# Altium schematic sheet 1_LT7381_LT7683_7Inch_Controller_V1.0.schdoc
size 431 x 309 mm; Symbol: Sheet-Symbol_A3; Device: Sheet-Symbol_A3; @Page Name: LT7381/LT7683_7Inch_Controller_V1.0; @Create Date: 2022-11-14; @Page Count: 1; @Page No: 1; @Project Name: LT7381(LT7683)_7Inch_Controller; @Schematic Name: LT7381/LT7683_7Inch_Controller_V1.0; @Update Date: 2023-04-10; Company: LEVETOP; Page Size: A3; Version: V1.0
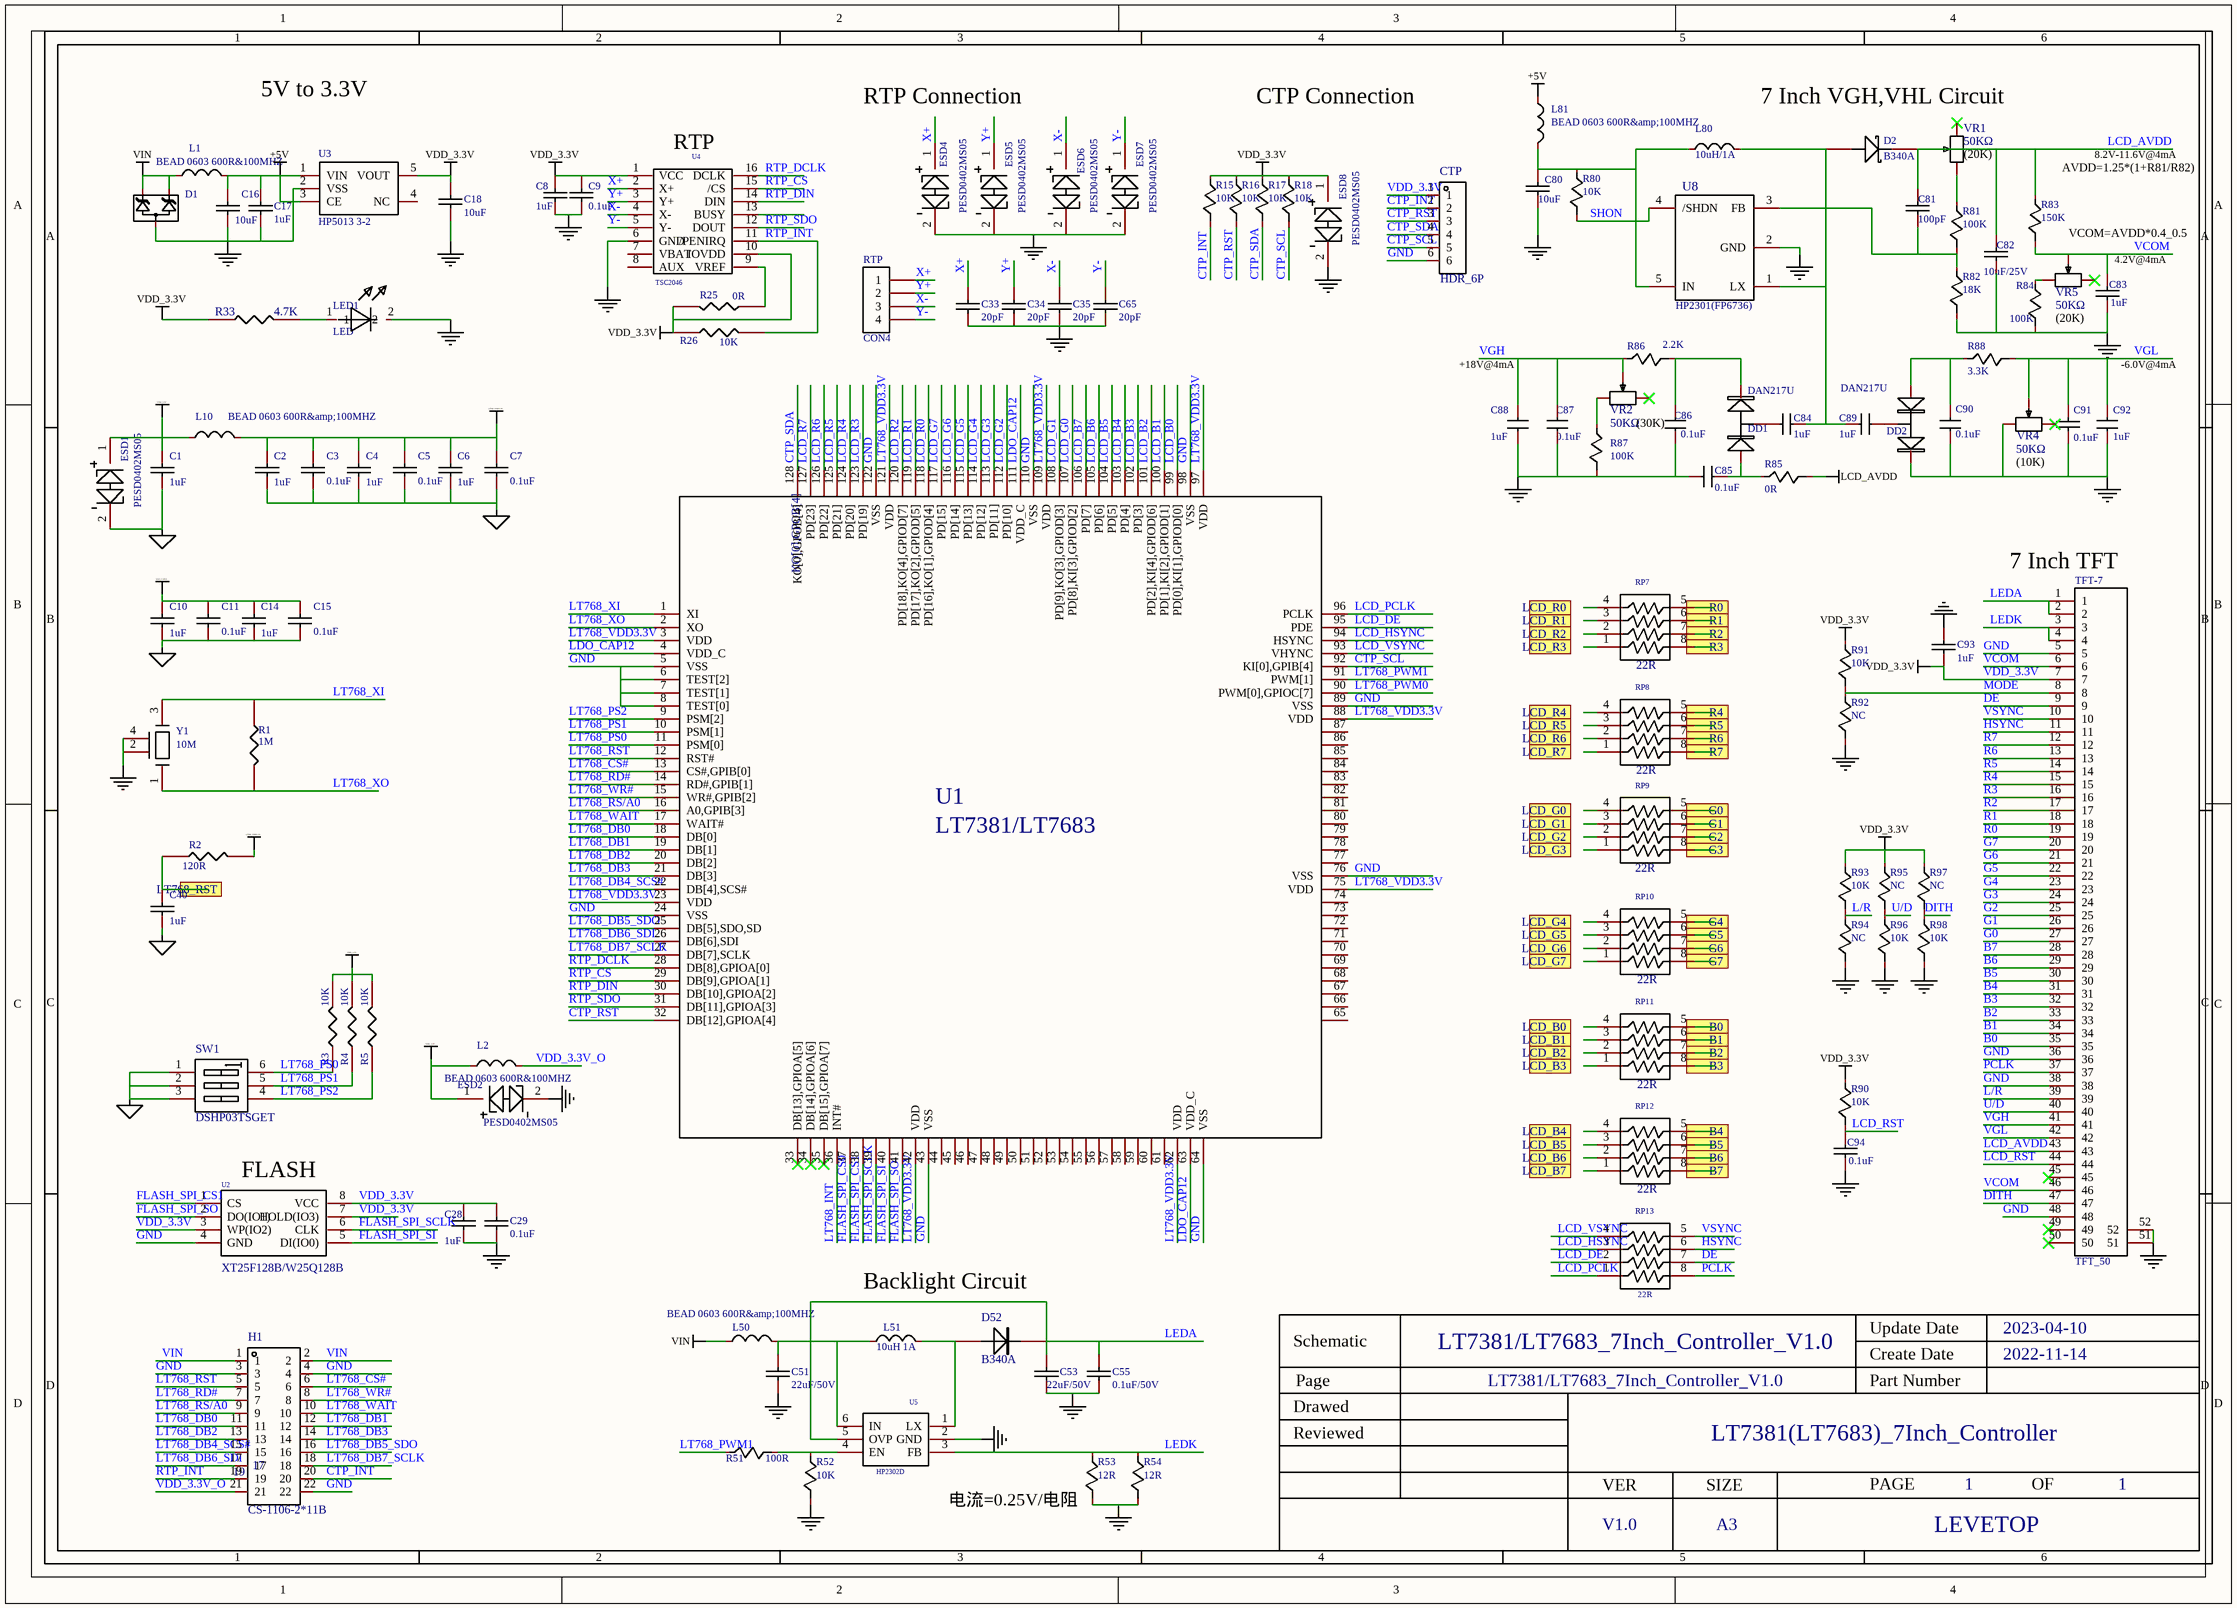
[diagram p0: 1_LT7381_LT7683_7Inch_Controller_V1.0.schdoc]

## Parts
C1  1uF  [C0603]
C2  1uF  [C0603]
C3  0.1uF  [C0603]
C4  1uF  [C0603]
C5  0.1uF  [C0603]
C6  1uF  [C0603]
C7  0.1uF  [C0603]
C8  1uF  [C0603]
C9  0.1uF  [C0603]
C10  1uF  [C0603]
C11  0.1uF  [C0603]
C14  1uF  [C0603]
C15  0.1uF  [C0603]
C16  10uF  [C0805]
C17  1uF  [C0603]
C18  10uF  [C0805]
C28  1uF  [C0603]
C29  0.1uF  [C0603]
C33  20pF  [C0603]
C34  20pF  [C0603]
C35  20pF  [C0603]
C40  1uF  [C0603]
C51  22uF/50V  [C0805_1]
C53  22uF/50V  [C0805_1]
C55  0.1uF/50V  [C0603]
C65  20pF  [C0603]
C80  10uF  [C0603]
C81  100pF  [C0603]
C82  10uF/25V  [C0603]
C83  1uF  [C0603]
C84  1uF  [C0603]
C85  0.1uF  [C0603]
C86  0.1uF  [C0603]
C87  0.1uF  [C0603]
C88  1uF  [C0603]
C89  1uF  [C0603]
C90  0.1uF  [C0603]
C91  0.1uF  [C0603]
C92  1uF  [C0603]
C93  1uF  [C0603]
C94  0.1uF  [C0603]
CTP  HDR_6P  [SIP-6P]
D1  MMBZ5V6A  [SOT-23]  (value not drawn)
D2  B340A  [DO-214]
D52  B340A  [DO-214]
DD1  DAN217U  [SOT23]
DD2  DAN217U  [SOT23]
ESD1  PESD0402MS05  [ESD0402]
ESD2  PESD0402MS05  [ESD0402]
ESD4  PESD0402MS05  [ESD0402]
ESD5  PESD0402MS05  [ESD0402]
ESD6  PESD0402MS05  [ESD0402]
ESD7  PESD0402MS05  [ESD0402]
ESD8  PESD0402MS05  [ESD0402]
H1  NUMBER: 19  NAME: 17  [HDR-TH_22P-P2.54-V-M-R2-C11-S2.54]  (hidden comment: CS-1106-2*11B)
L1  BEAD 0603 600R&100MHZ  [L0603]
L2  BEAD 0603 600R&100MHZ  [L0603]
L10  BEAD 0603 600R&amp;100MHZ  [L0603]
L50  BEAD 0603 600R&amp;100MHZ  [L0603]
L51  10uH 1A  [IND8A]
L80  10uH/1A  [IND8A]
L81  BEAD 0603 600R&amp;100MHZ  [L0603]
LED1  LED  [0603LED]
R1  1M  [R0603]
R2  120R  [R0603]
R3  10K  [R0603]
R4  10K  [R0603]
R5  10K  [R0603]
R15  10K  [R0603]
R16  10K  [R0603]
R17  10K  [R0603]
R18  10K  [R0603]
R25  0R  [R0603]
R26  10K  [R0603]
R33  4.7K  [R0603]
R51  100R  [R0603]
R52  10K  [R0603]
R53  12R  [R0603]
R54  12R  [R0603]
R80  10K  [R0603]
R81  100K  [R0603]
R82  18K  [R0603]
R83  150K  [R0603]
R84  100K  [R0603]
R85  0R  [R0603]
R86  2.2K  [R0603]
R87  100K  [R0603]
R88  3.3K  [R0603]
R90  10K  [R0603]
R91  10K  [R0603]
R92  NC  [R0603]
R93  10K  [R0603]
R94  NC  [R0603]
R95  NC  [R0603]
R96  10K  [R0603]
R97  NC  [R0603]
R98  10K  [R0603]
RP7  22R  [8R4R]
RP8  22R  [8R4R]
RP9  22R  [8R4R]
RP10  22R  [8R4R]
RP11  22R  [8R4R]
RP12  22R  [8R4R]
RP13  22R  [8R4R]
RTP  CON4  [SIP-4P]
SW1  DSHP03TSGET  [SW-SMD_6P-L5.4-W5.4-P1.27-LS8.4]
TFT-7  TFT_50  [FPC50-0.5]
U1  OldName: LT7381/LT7683  NAME: KO[0],GPOB[4]  [LQFP128L]  (hidden comment: LT768-136)
U2  XT25F128B/W25Q128B  [SOP-8A]
U3  HP5013 3-2  [SOT23-5]
U4  TSC2046  [TSSOP-16_L5.0-W4.4-P0.65-LS6.4-BL-1]
U5  HP2302D  [SOT23-6]
U8  HP2301(FP6736)  [SOT23-5]
VR1  50KΩ  [RES-ADJ-SMD_G32AT]
VR2  50KΩ  [RES-ADJ-SMD_G32AT]
VR4  50KΩ  [RES-ADJ-SMD_G32AT]
VR5  50KΩ  [RES-ADJ-SMD_G32AT]
Y1  10M  [M3225_1]

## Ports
B0 (in), B1 (in), B2 (in), B3 (in), B4 (in), B5 (in), B6 (in), B7 (in), G0 (in), G1 (in), G2 (in), G3 (in), G4 (in), G5 (in), G6 (in), G7 (in), LCD_B0 (in), LCD_B1 (in), LCD_B2 (in), LCD_B3 (in), LCD_B4 (in), LCD_B5 (in), LCD_B6 (in), LCD_B7 (in), LCD_G0 (in), LCD_G1 (in), LCD_G2 (in), LCD_G3 (in), LCD_G4 (in), LCD_G5 (in), LCD_G6 (in), LCD_G7 (in), LCD_R0 (in), LCD_R1 (in), LCD_R2 (in), LCD_R3 (in), LCD_R4 (in), LCD_R5 (in), LCD_R6 (in), LCD_R7 (in), LT768_RST (in), R0 (in), R1 (in), R2 (in), R3 (in), R4 (in), R5 (in), R6 (in), R7 (in)

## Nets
+5V: C16.1 C17.1 L1.2 L81.1 U3.1(VIN) U3.3(CE)
GND: C1.2 C2.2 C3.2 C4.2 C5.2 C6.2 C7.2 C8.2 C9.2 C10.2 C11.2 C14.2 C15.2 C16.2 C17.2 C18.2 C28.2 C29.2 C33.2 C34.2 C35.2 C40.2 C51.2 C53.2 C55.2 C65.2 C80.1 C82.1 C83.2 C85.1 C86.1 C87.2 C88.2 C90.1 C91.2 C92.2 C93.2 C94.2 CTP.6 D1.3(CA) DD2.2(K) ESD1.2 ESD2.2 ESD4.2 ESD5.2 ESD6.2 ESD7.2 ESD8.2 H1.3 H1.4 H1.22 LED1.2 R52.2 R53.2 R54.2 R82.2 R84.2 R87.2 R92.2 R94.2 R96.2 R98.2 SW1.1(A1) SW1.2(A2) SW1.3(A3) TFT-7.5 TFT-7.36 TFT-7.38 TFT-7.48 TFT-7.51 TFT-7.52 U1.5(VSS) U1.6(TEST[2]) U1.7(TEST[1]) U1.8(TEST[0]) U1.24(VSS) U1.43(VSS) U1.64(VSS) U1.76(VSS) U1.89(VSS) U1.98(VSS) U1.110(VSS) U1.122(VSS) U2.4(GND) U3.2(VSS) U4.6(GND) U5.2(GND) U8.2(GND) VR4.3 Y1.2 Y1.4
LCD_AVDD: C81.2 C82.2 D2.2(K) R83.1 R85.2 TFT-7.43 VR1.2
LDO_CAP12: C10.1 C11.1 C14.1 C15.1 U1.4(VDD_C) U1.63(VDD_C) U1.111(VDD_C)
LT768_VDD3.3V: C2.1 C3.1 C4.1 C5.1 C6.1 C7.1 L10.2 R2.2 U1.3(VDD) U1.23(VDD) U1.42(VDD) U1.62(VDD) U1.75(VDD) U1.88(VDD) U1.97(VDD) U1.109(VDD) U1.121(VDD)
VDD_3.3V: C1.1 C8.1 C9.1 C18.1 C28.1 C29.1 C93.1 CTP.1 ESD1.1 ESD2.1 ESD8.1 L2.1 L10.1 R3.2 R4.2 R5.2 R15.1 R16.1 R17.1 R18.1 R25.2 R26.1 R33.2 R90.1 R91.1 R93.1 R95.1 R97.1 TFT-7.7 U2.3(WP(IO2)) U2.7(HOLD(IO3)) U2.8(VCC) U3.5(VOUT) U4.1(VCC) U4.10(IOVDD)
VIN: D1.1(C1) D1.2(C2) H1.1 H1.2 L1.1 L50.1
B0: TFT-7.35
B1: TFT-7.34
B2: TFT-7.33
B3: TFT-7.32
B4: TFT-7.31
B5: TFT-7.30
B6: TFT-7.29
B7: TFT-7.28
CTP_INT: CTP.2 H1.20 R15.2
CTP_RST: CTP.3 R16.2 U1.32(DB[12],GPIOA[4])
CTP_SCL: CTP.5 R18.2 U1.92(KI[0],GPIB[4])
CTP_SDA: CTP.4 R17.2 U1.128(KO[0],GPOB[4])
DE: RP13.7 TFT-7.9
DITH: R97.2 R98.1 TFT-7.47
FLASH_SPI_CS0: U1.37(SFCS[0]#,GPIOC[3])
FLASH_SPI_CS1: U1.38(SFCS[1]#,GPIOC[4]) U2.1(CS)
FLASH_SPI_SCLK: U1.39(SFCLK,GPIOC[0]) U2.6(CLK)
FLASH_SPI_SI: U1.40(SFDO,GPIOC[1]) U2.5(DI(IO0))
FLASH_SPI_SO: U1.41(SFDI,GPIOC[2]) U2.2(DO(IO1))
G0: TFT-7.27
G1: TFT-7.26
G2: TFT-7.25
G3: TFT-7.24
G4: TFT-7.23
G5: TFT-7.22
G6: TFT-7.21
G7: TFT-7.20
HSYNC: RP13.6 TFT-7.11
L/R: R93.2 R94.1 TFT-7.39
LCD_B0: U1.99(PD[0],KI[1],GPIOD[0])
LCD_B1: U1.100(PD[1],KI[2],GPIOD[1])
LCD_B2: U1.101(PD[2],KI[4],GPIOD[6])
LCD_B3: U1.102(PD[3])
LCD_B4: U1.103(PD[4])
LCD_B5: U1.104(PD[5])
LCD_B6: U1.105(PD[6])
LCD_B7: U1.106(PD[7])
LCD_DE: RP13.2 U1.95(PDE)
LCD_G0: U1.107(PD[8],KI[3],GPIOD[2])
LCD_G1: U1.108(PD[9],KO[3],GPIOD[3])
LCD_G2: U1.112(PD[10])
LCD_G3: U1.113(PD[11])
LCD_G4: U1.114(PD[12])
LCD_G5: U1.115(PD[13])
LCD_G6: U1.116(PD[14])
LCD_G7: U1.117(PD[15])
LCD_HSYNC: RP13.3 U1.94(HSYNC)
LCD_PCLK: RP13.1 U1.96(PCLK)
LCD_R0: U1.118(PD[16],KO[1],GPIOD[4])
LCD_R1: U1.119(PD[17],KO[2],GPIOD[5])
LCD_R2: U1.120(PD[18],KO[4],GPIOD[7])
LCD_R3: U1.123(PD[19])
LCD_R4: U1.124(PD[20])
LCD_R5: U1.125(PD[21])
LCD_R6: U1.126(PD[22])
LCD_R7: U1.127(PD[23])
LCD_RST: C94.1 R90.2 TFT-7.44
LCD_VSYNC: RP13.4 U1.93(VHYNC)
LEDA: C53.1 C55.1 D52.2(K) TFT-7.1 TFT-7.2 U5.5(OVP)
LEDK: R53.1 R54.1 TFT-7.3 TFT-7.4 U5.3(FB)
LT768_CS#: H1.6 U1.13(CS#,GPIB[0])
LT768_DB0: H1.11 U1.18(DB[0])
LT768_DB1: H1.12 U1.19(DB[1])
LT768_DB2: H1.13 U1.20(DB[2])
LT768_DB3: H1.14 U1.21(DB[3])
LT768_DB4_SCS#: H1.15 U1.22(DB[4],SCS#)
LT768_DB5_SDO: H1.16 U1.25(DB[5],SDO,SD)
LT768_DB6_SDI: H1.17 U1.26(DB[6],SDI)
LT768_DB7_SCLK: H1.18 U1.27(DB[7],SCLK)
LT768_INT: U1.36(INT#)
LT768_PS0: R3.1 SW1.6(B1) U1.11(PSM[0])
LT768_PS1: R4.1 SW1.5(B2) U1.10(PSM[1])
LT768_PS2: R5.1 SW1.4(B3) U1.9(PSM[2])
LT768_PWM0: U1.90(PWM[0],GPIOC[7])
LT768_PWM1: R51.1 U1.91(PWM[1])
LT768_RD#: H1.7 U1.14(RD#,GPIB[1])
LT768_RS/A0: H1.9 U1.16(A0,GPIB[3])
LT768_RST: H1.5 U1.12(RST#)
LT768_RST: C40.1 R2.1 ; port LT768_RST  [a separate net that carries the same name]
LT768_WAIT: H1.10 U1.17(WAIT#)
LT768_WR#: H1.8 U1.15(WR#,GPIB[2])
LT768_XI: R1.1 U1.1(XI) Y1.3
LT768_XO: R1.2 U1.2(XO) Y1.1
MODE: R91.2 R92.1 TFT-7.8
PCLK: RP13.8 TFT-7.37
R0: TFT-7.19
R1: TFT-7.18
R2: TFT-7.17
R3: TFT-7.16
R4: TFT-7.15
R5: TFT-7.14
R6: TFT-7.13
R7: TFT-7.12
RTP_CS: U1.29(DB[9],GPIOA[1]) U4.15(/CS)
RTP_DCLK: U1.28(DB[8],GPIOA[0]) U4.16(DCLK)
RTP_DIN: U1.30(DB[10],GPIOA[2]) U4.14(DIN)
RTP_INT: H1.19 R26.2 U4.11(/PENIRQ)
RTP_SDO: U1.31(DB[11],GPIOA[3]) U4.12(DOUT)
SHON: R80.2 U8.4(/SHDN)
U/D: R95.2 R96.1 TFT-7.40
VCOM: C83.1 R83.2 TFT-7.6 TFT-7.46 VR5.2
VDD_3.3V_O: H1.21 L2.2
VGH: C87.1 C88.1 R86.1 TFT-7.41 VR2.2
VGL: C91.1 C92.1 R88.2 TFT-7.42 VR4.2
VSYNC: RP13.5 TFT-7.10
X+: C33.1 ESD4.1 RTP.1 U4.2(X+)
X-: C35.1 ESD6.1 RTP.3 U4.4(X-)
Y+: C34.1 ESD5.1 RTP.2 U4.3(Y+)
Y-: C65.1 ESD7.1 RTP.4 U4.5(Y-)
NetC51_1: C51.1 L50.2 L51.1 U5.6(IN)
NetC80_2: C80.2 L80.1 L81.2 R80.1 U8.5(IN)
NetC81_1: C81.1 R81.2 R82.1 U8.3(FB)
NetC84_1: C84.1 DD1.3(C)
NetC84_2: C84.2 C89.1 D2.1(A) L80.2 U8.1(LX)
NetC85_2: C85.2 DD1.1(A) R85.1
NetC86_2: C86.2 DD1.2(K) R86.2
NetC89_2: C89.2 DD2.3(C)
NetC90_2: C90.2 DD2.1(A) R88.1
NetD52_1: D52.1(A) L51.2 U5.1(LX)
NetLED1_1: LED1.1 R33.1
NetR25_1: R25.1 U4.9(VREF)
NetR51_2: R51.2 R52.1 U5.4(EN)
NetR81_1: R81.1 VR1.3
NetR84_1: R84.1 VR5.3
NetR87_1: R87.1 VR2.3

Not connected (* = marked no-connect by the designer): RP7 1 2 3 4 5 6 7 8; RP8 1 2 3 4 5 6 7 8; RP9 1 2 3 4 5 6 7 8; RP10 1 2 3 4 5 6 7 8; RP11 1 2 3 4 5 6 7 8; RP12 1 2 3 4 5 6 7 8; TFT-7 45* 49* 50*; U1 33(DB[13],GPIOA[5])* 34(DB[14],GPIOA[6])* 35(DB[15],GPIOA[7])* 44(NC) 45(NC) 46(NC) 47(NC) 48(NC) 49(NC) 50(NC) 51(NC) 52(NC) 53(NC) 54(NC) 55(NC) 56(NC) 57(NC) 58(NC) 59(NC) 60(NC) 61(NC) 65(NC) 66(NC) 67(NC) 68(NC) 69(NC) 70(NC) 71(NC) 72(NC) 73(NC) 74(NC) 77(NC) 78(NC) 79(NC) 80(NC) 81(NC) 82(NC) 83(NC) 84(NC) 85(NC) 86(NC) 87(NC); U3 4(NC); U4 7(VBAT) 8(AUX) 13(BUSY); VR1 1*; VR2 1*; VR4 1*; VR5 1*

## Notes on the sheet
- 5V to 3.3V
- RTP Connection
- CTP Connection
- 7 Inch VGH,VHL Circuit
- (near U4) RTP
- (near VR1) (20K)
- (near R83) AVDD=1.25*(1+R81/R82)
- 8.2V-11.6V@4mA
- VCOM=AVDD*0.4_0.5
- (20K)
- 4.2V@4mA
- +18V@4mA
- -6.0V@4mA
- (near C86) (30K)
- (10K)
- (near TFT-7) 7 Inch TFT
- (near U2) FLASH
- Backlight Circuit
- 电流=0.25V/电阻

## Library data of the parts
C1-C7 C10 C11 C14 C15 C28 C29 C40 C55 C80-C83 C91 C93 C94 = CAP_C0603: Capacitor; Symbol: CAP; Add into BOM: yes
C8 C9 C33-C35 C65 = CAP_C0603: Capacitor; Symbol: CAP; Add into BOM: yes; Origin Footprint 2: 0603
C16 C18 = CAP_CAP_0805: Capacitor; Symbol: CAP; Origin Footprint 2: 0805; Add into BOM: yes
C17 = CAP_C0603: Capacitor; Symbol: CAP; Origin Footprint 2: 0603; Add into BOM: yes
C51 C53 = CAP_C0805: Capacitor; Symbol: CAP; Origin Footprint: C0805; Add into BOM: yes
C84-C90 C92 = CAP_C0603(1)_1: Capacitor; Symbol: CAP(2); Add into BOM: yes
CTP = 排针 2.54mm 1*60P直排针: Connector; Symbol: Header-Female-2.54_1x6; Add into BOM: yes
D1 = ESD7C3.3DT5G: Diode; Origin Footprint 2: SOT-723; Add into BOM: yes
D2 = DIODE SCHOTTKY: Schottky Diode; Origin Footprint: SOD-323; Add into BOM: yes
D52 = DIODE(1): Diode; Pin Type: IN; Add into BOM: yes; Origin Footprint 2: SOD-323
DD1 = DAN217U: Diode ACK; Origin Footprint: SOT-23; Add into BOM: yes
DD2 = DAN217U_SOT-23: Diode ACK; Origin Footprint: SOT-23; Add into BOM: yes
ESD1 ESD2 ESD4-ESD8 = ESD5621W15_ESD0402: ESD; Add into BOM: yes
H1 = CS-1106-2*11B: Header; Manufacturer: CST(永丰盈); Add into BOM: yes; Pitch: 2.54mm; Pin Structure: 2x11P; Circluar Pins/Square Pins: 方针; Current Rating (Max): 3A; Voltage Rating (Max): 250V
L1 L2 L10 L81 = IND_R0603: BEAD; Symbol: IND; Origin Footprint: R0603; Add into BOM: yes
L50 = IND: BEAD; Origin Footprint: R0603; Add into BOM: yes
L51 L80 = IND_IND8A: Industance; Symbol: IND; Add into BOM: yes
LED1 = LED_1: Add into BOM: yes
R1 = RES1: Resistance; Add into BOM: yes
R2-R5 R33 = RES1_R0603: Resistance; Symbol: RES1; Add into BOM: yes
R15-R18 R51-R54 R80-R88 R90-R98 = RES_R0603: Resistance; Symbol: RES; Add into BOM: yes
R25 R26 = RES1_R0603: Resistance; Symbol: RES1; Add into BOM: yes; Origin Footprint 2: 0603
RP7-RP12 = RP4: Resistor Packs; Symbol: RP-4; Add into BOM: yes; Value: 100R
RP13 = RP4: Resistor Packs; Symbol: RP-4; Add into BOM: yes
RTP = CON4: Header; Add into BOM: yes
SW1 = DSHP03TSGET: Switch; Manufacturer: YE; Symbol: DSHP03TSGER; Add into BOM: yes; Circuit: 单刀单掷; Number of Positions: 3
TFT-7 = TFT_50: Connector; Add into BOM: yes
U1 = LT768-136: IC; Symbol: LQFP128; Add into BOM: yes
U2 = W25Q64BVSIG: IC; Add into BOM: yes
U3 = HP5013 3-2: IC; Add into BOM: yes
U4 = TSC2046: IC; PCB DECAL: TSSOP-16; Add into BOM: yes
U5 = G5126: IC; Add into BOM: yes
U8 = FP6736: IC; Add into BOM: yes
VR1 VR2 VR4 VR5 = G32AT-B503: RES-ADJ; Manufacturer: TOCOS; Add into BOM: yes; Tolerance: ±20%; Power(Watts): 0.125W; Temperature Coefficient: ±100ppm/; Turns: 1; Rated Voltage: 200V
Y1 = CRY_SJK: Origin Footprint: M3225; Add into BOM: yes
